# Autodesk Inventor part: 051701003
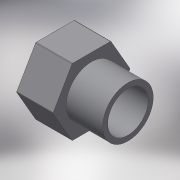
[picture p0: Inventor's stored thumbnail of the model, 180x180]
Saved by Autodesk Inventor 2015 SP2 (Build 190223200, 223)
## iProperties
Created: 2017-10
Part Number: 051701003
Material: Generic
Description: PLASSON THREADED PLUG PVC 3/8"
Document SubType Name: Modeling
Designer: KIM
Density: 1 g/cm^3
Appearance: Default
Author: KIM
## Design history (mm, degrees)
derived "051701.ipt"
feature "Solid1::051701.ipt"
tag "TaggingFeature1"
body "Solid1"
other parameters: "d0" = 25, "d1" = 16.662, "d2" = 1, "d3" = 12, "d4" = 22, "d6" = 13.3296, "d9" = 12, "d10" = 0, "d18" = 0.22, "d19" = 12, "d20" = 17.5, "R_" = 16.662, "C_" = 22, "B_" = 12, "Lt_" = 12, "H_" = 25
